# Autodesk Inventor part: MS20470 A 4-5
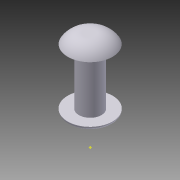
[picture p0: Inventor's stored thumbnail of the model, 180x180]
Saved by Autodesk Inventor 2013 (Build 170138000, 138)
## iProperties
Created: 2004-10
Part Number: MS20470 A 4-5
Material: Aluminium - 6061
Description: #4 x 0.313 RIVET, SOLID, UNIVERSAL HEAD
Document SubType Name: Modeling
Designer: Autodesk, Inc.
Manufacturer: Standard
Standards Organization: Custom
Mass: 0.0360393 g
Surface Area: 0.509577 cm^2
Volume: 0.0132986 cm^3
Density: 2.71 g/cm^3
CAGE: 1LJX3
Dept. ID: Product Design
Description #2: ---
Finish #1: ---
Finish #2: ---
Material ID: ---
Project Number: ---
Author: Autodesk, Inc.
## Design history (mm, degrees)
derived "MS204xx Rivets.ipt"
body "Solid1"
tag "TaggingFeature2"
feature "Solid1::MS204xx Rivets.ipt" dims "ScaleForDerivedMember" = 10
